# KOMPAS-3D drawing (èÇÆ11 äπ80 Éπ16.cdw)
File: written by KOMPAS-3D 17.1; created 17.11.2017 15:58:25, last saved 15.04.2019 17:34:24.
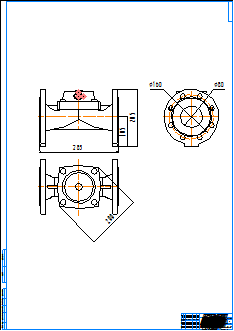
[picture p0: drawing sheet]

Sheet 1: A0, portrait

Title block, sheet 1: name: КАТ11 Ду80 Ру16; material: Внимание! Данный продукт является объектом авторского права ООО «Торговый Дом АДЛ». / Запрещается изменение, копирование, распространение / (в том числе путем копирования на другие сайты и ресурсы в Интернете) / или любое иное использование информации и объектов без предварительного / согласия правообладателя (ООО «Торговый Дом АДЛ»).; mass: 12,4; sheets: 1; organisation: ООО "Торговый дом АДЛ"; sheet format: A0; stored path: \\adlc.lan\data\АДЛ_ПКД\3D-модели\ADL production\Клапаны КАТ ГРАНРЕГ\КАТ11\KOMPAS 2D\КАТ11 Ду80 Ру16.cdw

Views: Вид 1, Проекционный вид 2, Проекционный вид 3
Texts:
  kka
  adl
Dimensions and other numbers on the sheet: 285; 105; 205; 160; 80; 200; 1:1; 1; 12,4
